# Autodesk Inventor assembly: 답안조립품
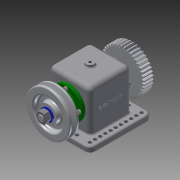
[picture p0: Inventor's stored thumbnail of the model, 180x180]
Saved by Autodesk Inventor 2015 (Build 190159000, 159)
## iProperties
Created: 2018-11
Part Number: 답안조립품
Document SubType Name: Assembly
Designer: now333
Author: now333
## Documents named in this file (13)
- C:\Users\now333\Desktop\481108V1011\답안조립품.iam
- C:\Users\now333\Desktop\481108V1011\V벨트풀리.ipt
- C:\Users\now333\Desktop\481108V1011\너트 M12x1.25.ipt
- C:\Users\now333\Desktop\481108V1011\베어링 6203.ipt
- C:\Users\now333\Desktop\481108V1011\본체.ipt
- C:\Users\now333\Desktop\481108V1011\볼트 M4.ipt
- C:\Users\now333\Desktop\481108V1011\부시.ipt
- C:\Users\now333\Desktop\481108V1011\스퍼기어.ipt
- C:\Users\now333\Desktop\481108V1011\오일 실 26 38 8.ipt
- C:\Users\now333\Desktop\481108V1011\와셔 12x24.ipt
- C:\Users\now333\Desktop\481108V1011\축.ipt
- C:\Users\now333\Desktop\481108V1011\커버.ipt
- C:\Users\now333\Desktop\481108V1011\키 5x5x12.ipt
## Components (1 placed, 1 different names)
1. V벨트풀리:1 — 각도:3
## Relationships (1: Angle 1)
- 각도:3 [Angle]: V벨트풀리:1
